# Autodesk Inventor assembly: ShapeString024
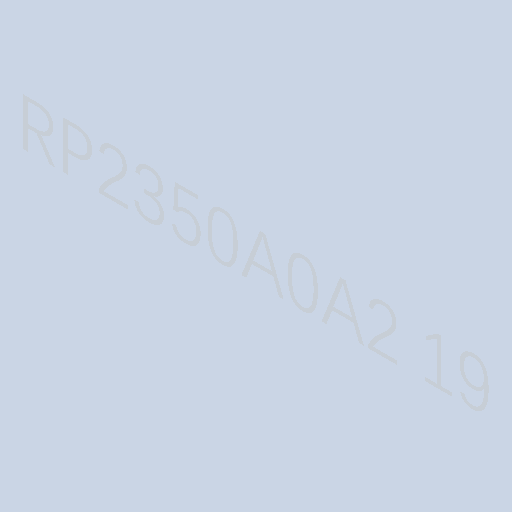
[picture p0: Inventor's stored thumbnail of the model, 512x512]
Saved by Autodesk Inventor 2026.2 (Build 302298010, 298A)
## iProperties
Created: 2026-10
Part Number: ShapeString024
Document SubType Name: Assembly
Designer: mel
Author: mel
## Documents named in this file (13)
- D:\travail\année 2026-2027\1 sti2d IT\poubelle à verre\raspberry-pico-2-microcontroller-rp2350-1.snapshot.5\raspberry_pico_2\raspberry_pico_2\ShapeString024.iam
- D:\travail\année 2026-2027\1 sti2d IT\poubelle à verre\raspberry-pico-2-microcontroller-rp2350-1.snapshot.5\raspberry_pico_2\raspberry_pico_2\ShapeString.ipt
- D:\travail\année 2026-2027\1 sti2d IT\poubelle à verre\raspberry-pico-2-microcontroller-rp2350-1.snapshot.5\raspberry_pico_2\raspberry_pico_2\ShapeString013.ipt
- D:\travail\année 2026-2027\1 sti2d IT\poubelle à verre\raspberry-pico-2-microcontroller-rp2350-1.snapshot.5\raspberry_pico_2\raspberry_pico_2\ShapeString014.ipt
- D:\travail\année 2026-2027\1 sti2d IT\poubelle à verre\raspberry-pico-2-microcontroller-rp2350-1.snapshot.5\raspberry_pico_2\raspberry_pico_2\ShapeString015.ipt
- D:\travail\année 2026-2027\1 sti2d IT\poubelle à verre\raspberry-pico-2-microcontroller-rp2350-1.snapshot.5\raspberry_pico_2\raspberry_pico_2\ShapeString016.ipt
- D:\travail\année 2026-2027\1 sti2d IT\poubelle à verre\raspberry-pico-2-microcontroller-rp2350-1.snapshot.5\raspberry_pico_2\raspberry_pico_2\ShapeString017.ipt
- D:\travail\année 2026-2027\1 sti2d IT\poubelle à verre\raspberry-pico-2-microcontroller-rp2350-1.snapshot.5\raspberry_pico_2\raspberry_pico_2\ShapeString018.ipt
- D:\travail\année 2026-2027\1 sti2d IT\poubelle à verre\raspberry-pico-2-microcontroller-rp2350-1.snapshot.5\raspberry_pico_2\raspberry_pico_2\ShapeString019.ipt
- D:\travail\année 2026-2027\1 sti2d IT\poubelle à verre\raspberry-pico-2-microcontroller-rp2350-1.snapshot.5\raspberry_pico_2\raspberry_pico_2\ShapeString020.ipt
- D:\travail\année 2026-2027\1 sti2d IT\poubelle à verre\raspberry-pico-2-microcontroller-rp2350-1.snapshot.5\raspberry_pico_2\raspberry_pico_2\ShapeString021.ipt
- D:\travail\année 2026-2027\1 sti2d IT\poubelle à verre\raspberry-pico-2-microcontroller-rp2350-1.snapshot.5\raspberry_pico_2\raspberry_pico_2\ShapeString022.ipt
- D:\travail\année 2026-2027\1 sti2d IT\poubelle à verre\raspberry-pico-2-microcontroller-rp2350-1.snapshot.5\raspberry_pico_2\raspberry_pico_2\ShapeString023.ipt
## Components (12 placed, 12 different names)
1. 2677
2. 2678
3. 2679
4. 2680
5. 2681
6. 2682
7. 2683
8. 2684
9. 2685
10. 2686
11. 2687
12. 2688
